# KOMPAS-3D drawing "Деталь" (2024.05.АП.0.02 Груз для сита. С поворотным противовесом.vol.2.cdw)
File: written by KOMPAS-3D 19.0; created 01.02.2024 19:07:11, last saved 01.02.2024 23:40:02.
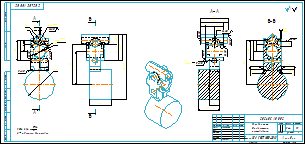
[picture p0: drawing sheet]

Sheet 1: A4x3, landscape

Document properties: Автор: mail.maksim@mail.ru; Знак неуказанной шероховатости: 6; Масса: 1.43725; Наименование: Груз для сита. С поворотным противовесом; Форматы листов документа: A4@4~3

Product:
- Part/product: Деталь
    Масса: 1.43725

Title block, sheet 1: Наименование: Груз для сита. / С поворотным / противовесом.; designation: 2024.05.АП.0.02; Материал: Сталь 35Л  ГОСТ 1050-2013; Масса: 1,44; Количество листов документа: 1; organisation: АгроПак; Форматы листов документа: A4 3; stored path: O:\Самозанятый. Полынский М.И\Агропак\04 Проекты 2024 года\2024.05.АП.00.00 Грузы для сита. Хартманн 1 и 2\2024.05.АП.00.00 Чертежи\2024.05.АП 2D чертежи\2024.05.АП.0.02 Груз для сита. С поворотным противовесом.vol.2.cdw; Разработал: Полынский; Утвердил: Гордиенко

Views: Спереди 1
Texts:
  Rz20
  сквозное
Dimensions and other numbers on the sheet: 25,15; 12; 2,5; 1,25; 38; 36; 24; 8; 16; 18; 1; 23; 62; 35; 19,43; 54,43; 84,5; 68,5; 45; 57; 37; 10; 18,5; 28,5; 22; 12,5; 8 фасок; 134,93; 42; 92,5; 6,5; 6,48; 0,5; 1:1; 1,44; 2024.05.АП.0.02; 2024.05.АП.0.02-

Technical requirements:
  * - Размеры для справки.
